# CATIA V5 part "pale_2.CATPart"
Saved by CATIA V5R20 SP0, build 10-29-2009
Part number: pale_2
Bounding box of the stored display mesh (mm): x 655.778 to 2705.778, y -779.513 to -272.061, z -1010.959 to -143.809
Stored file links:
  D:\thinkmotion-MPB\Dropbox\MMS_GR3\CFAO_2010_bfoltzer\CFAO_bfoltzer\pale_2.CATPart
  D:\ecole\thinkmotion\Eolienne.CATProduct
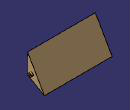
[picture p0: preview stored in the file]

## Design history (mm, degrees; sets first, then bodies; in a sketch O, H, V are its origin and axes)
External parameters (linked from other documents)
  External.rayon_barre = 20 mm
  External.largeur_pale = 300 mm
Set1
  Plane1: linked copy from another document
  Point1 to Point4: linked copy from another document
  Plane2: linked copy from another document
  Point5: linked copy from another document
  Plane3: linked copy from another document
  Plane4: linked copy from another document
  Point6: linked copy from another document
  Plane5: linked copy from another document
Body1 (main body)
  Sketch1 on Plane1, origin (655.7782, 0, 0), H (0, 1, 0), V (0, 0, 1)
    line L1 (-770.108, -143.8088) -> (-781.2298, -726.7979)
    point P1 (-770.108, -143.8088)
    point P2 (-781.2298, -726.7979)
    reference projected point E1 (-770.108, -143.8088) from Point2
    reference projected point E2 (-781.2298, -726.7979) from Point1
    line L2 (-781.2298, -726.7979) -> (-272.0614, -1010.9591)
    point P3 (-781.2298, -726.7979)
    point P4 (-272.0614, -1010.9591)
    reference projected point E3 (-272.0614, -1010.9591) from Point3
    reference projected point E4 (-781.2298, -726.7979) from Point6
    line L3 (-770.108, -143.8088) -> (-272.0614, -1010.9591)
    point P5 (-770.108, -143.8088)
    point P6 (-272.0614, -1010.9591)
    reference projected point E5 (-272.0614, -1010.9591) from Point3
    reference projected point E6 (-770.108, -143.8088) from Point2
    coincidence: P1 E1, P2 E2, P4 E3, P3 E4, P6 E5, P5 E6, P1 P5, P2 P3, P4 P6
  Pad1: profile Sketch1, direction (1, 0, 0), up to Plane2, opposite side up to Plane1
  Fillet1: radius 150 {= External.largeur_pale /2}, on edge [face of Pad1 from Sketch1.L2 | face of Pad1 from Sketch1.L1]
  Sketch2 on Plane1, origin (655.7782, 0, 0), H (0, 1, 0), V (0, 0, 1)
    circle A1 centre (-651.1573, -652.091) radius 50
    point P1 (-651.1573, -652.091)
    reference projected point E1 (-651.1573, -652.091) from Point4
    reference projected point E2 (-694.5148, -676.9933) from Point5
    coincidence: P1 E1, A1 E2
  Pad2: profile Sketch2, direction (1, 0, 0), up to Plane2, opposite side up to Plane4
  Pocket1: profile Sketch2, direction (-1, 0, 0), up to Plane1, opposite side up to Plane3
  Sketch3 on start face of Pocket1, origin (705.7782, 744.3932, 992.3738), H (0, 1, 0), V (0, 0, -1)
    point P1 (-1395.5504, 1644.4648)
    reference projected point E1 (-1395.5504, 1644.4648) from Point4
    coincidence: E1 P1
  Hole1: placed by Sketch3, at (705.7782, -651.1573, -652.091) direction (1, 0, 0), diameter 40 {= External.rayon_barre *2}, up to Plane4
